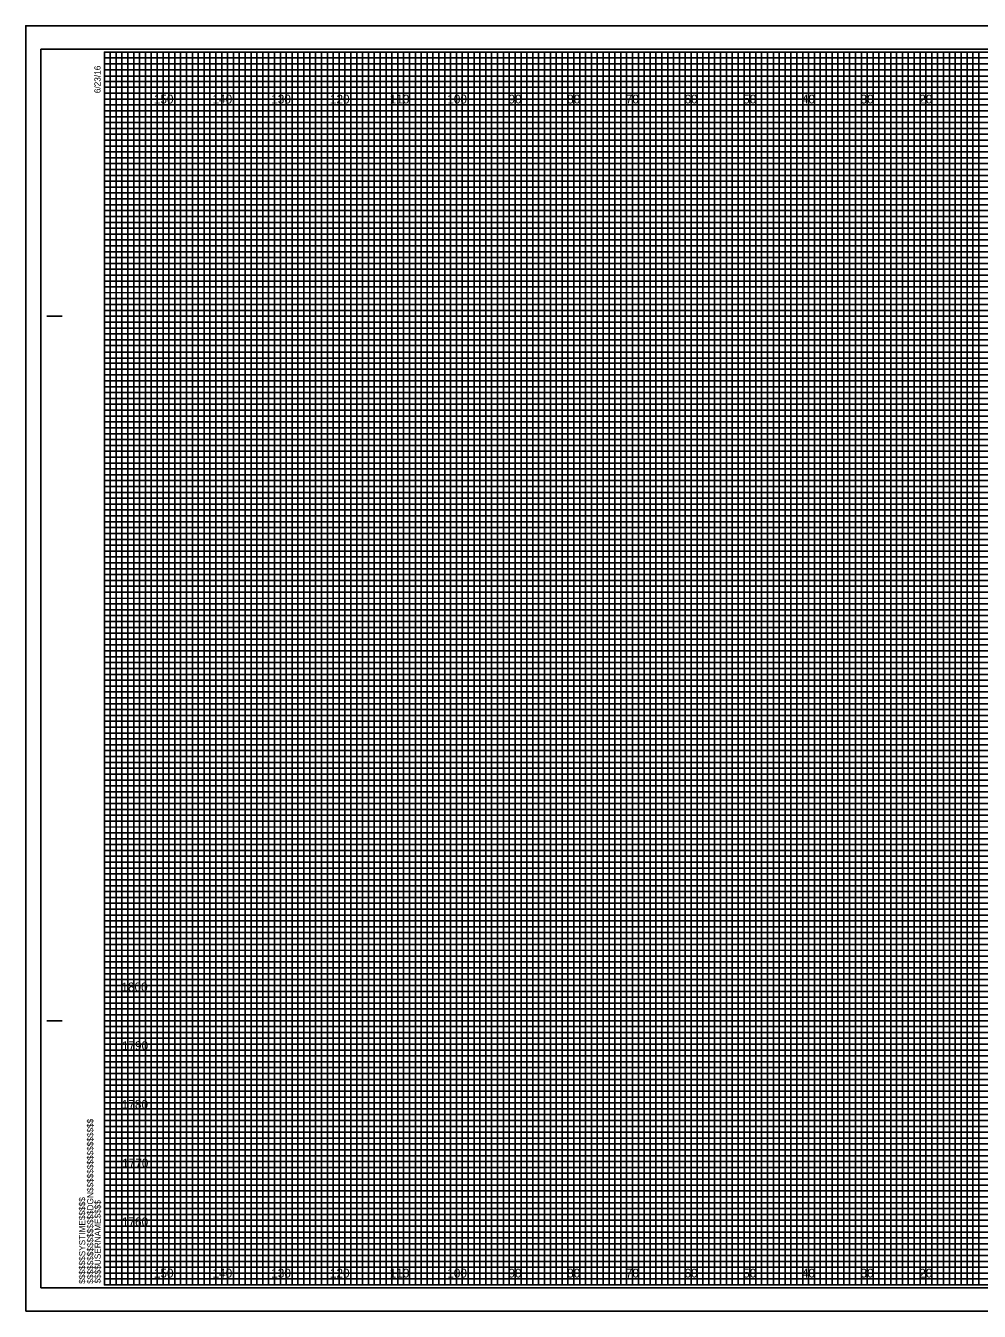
# Model space of a CAD drawing. Extents: x -412 to -75, y -2 to 657.
# Drawn here: x -412.2 to -249.7, y 438.1 to 657.1 of the extents above; entities that cross this region are included whole.
import ezdxf

# ---------------------------------------------------------------- set-up
doc = ezdxf.new("R2010")
doc.units = 0
for name, color, linetype in [('Prop XS Elevation Labels', 7, 'Continuous'), ('Prop XS Offset Labels', 7, 'Continuous'), ('Sheet Cross Section CELL', 7, 'Continuous'), ('Sheet Cross Section Grid Major CELL', 7, 'Continuous'), ('Sheet Cross Section Grid Middle CELL', 7, 'Continuous'), ('Sheet Cross Section Grid Minor 1 CELL', 7, 'Continuous'), ('Sheet Cross Section Grid Minor 2 CELL', 7, 'Continuous'), ('Sheet Cutting Line CELL', 7, 'Continuous'), ('Sheet DOT Grid CELL', 7, 'Continuous'), ('Sheet Plot Border Inside CELL', 7, 'Continuous'), ('Sheet Plot Border Outside CELL', 7, 'Continuous')]:
    doc.layers.add(name, color=color, linetype=linetype)

msp = doc.modelspace()

# ---------------------------------------------------------------- linework, layer by layer
at = {"layer": 'Sheet Cross Section CELL'}
for p, q in [((-408.55, 607.57), (-406.05, 607.57)), ((-408.45, 607.57), (-405.95, 607.57)), ((-408.55, 487.57), (-406.05, 487.57)), ((-408.45, 487.57), (-405.95, 487.57)), ((-398.75, 442.57), (-398.75, 442.57)), ((-398.75, 442.57), (-398.75, 442.57)), ((-398.75, 442.57), (-398.75, 442.57)), ((-398.75, 442.57), (-398.75, 442.57)), ((-398.75, 442.57), (-398.75, 442.57)), ((-398.75, 442.57), (-398.75, 442.57)), ((-398.75, 442.57), (-398.75, 442.57))]:
    msp.add_line(p, q, dxfattribs=at)
msp.add_lwpolyline([(-78.75, 652.57), (-398.75, 652.57), (-398.75, 442.57), (-78.75, 442.57)], close=True, dxfattribs=at)
at = {"layer": 'Sheet Cross Section Grid Major CELL'}
for p, q in [((-388.75, 652.57), (-398.75, 652.57)), ((-388.75, 442.57), (-388.75, 652.57)), ((-368.75, 652.57), (-378.75, 652.57)), ((-378.75, 652.57), (-378.75, 442.57)), ((-368.75, 442.57), (-368.75, 652.57)), ((-348.75, 652.57), (-358.75, 652.57)), ((-358.75, 652.57), (-358.75, 442.57)), ((-348.75, 442.57), (-348.75, 652.57)), ((-328.75, 652.57), (-338.75, 652.57)), ((-338.75, 652.57), (-338.75, 442.57)), ((-328.75, 442.57), (-328.75, 652.57)), ((-308.75, 652.57), (-318.75, 652.57)), ((-318.75, 652.57), (-318.75, 442.57)), ((-308.75, 442.57), (-308.75, 652.57)), ((-288.75, 652.57), (-298.75, 652.57)), ((-298.75, 652.57), (-298.75, 442.57)), ((-288.75, 442.57), (-288.75, 652.57)), ((-268.75, 652.57), (-278.75, 652.57)), ((-278.75, 652.57), (-278.75, 442.57)), ((-268.75, 442.57), (-268.75, 652.57)), ((-248.75, 652.57), (-258.75, 652.57)), ((-258.75, 652.57), (-258.75, 442.57)), ((-378.75, 442.57), (-388.75, 442.57)), ((-358.75, 442.57), (-368.75, 442.57)), ((-338.75, 442.57), (-348.75, 442.57)), ((-318.75, 442.57), (-328.75, 442.57)), ((-298.75, 442.57), (-308.75, 442.57)), ((-278.75, 442.57), (-288.75, 442.57)), ((-258.75, 442.57), (-268.75, 442.57))]:
    msp.add_line(p, q, dxfattribs=at)
for points in [[(-398.75, 642.57), (-78.75, 642.57), (-78.75, 632.57), (-398.75, 632.57)], [(-398.75, 622.57), (-78.75, 622.57), (-78.75, 612.57), (-398.75, 612.57)], [(-398.75, 602.57), (-78.75, 602.57), (-78.75, 592.57), (-398.75, 592.57)], [(-398.75, 582.57), (-78.75, 582.57), (-78.75, 572.57), (-398.75, 572.57)], [(-398.75, 562.57), (-78.75, 562.57), (-78.75, 552.57), (-398.75, 552.57)], [(-398.75, 542.57), (-78.75, 542.57), (-78.75, 532.57), (-398.75, 532.57)], [(-398.75, 522.57), (-78.75, 522.57), (-78.75, 512.57), (-398.75, 512.57)], [(-398.75, 502.57), (-78.75, 502.57), (-78.75, 492.57), (-398.75, 492.57)], [(-398.75, 482.57), (-78.75, 482.57), (-78.75, 472.57), (-398.75, 472.57)], [(-398.75, 462.57), (-78.75, 462.57), (-78.75, 452.57), (-398.75, 452.57)]]:
    msp.add_lwpolyline(points, dxfattribs=at)
at = {"layer": 'Sheet Cross Section Grid Middle CELL'}
for points in [[(-398.75, 652.57), (-393.75, 652.57), (-393.75, 442.57), (-383.75, 442.57), (-383.75, 652.57), (-373.75, 652.57), (-373.75, 442.57), (-363.75, 442.57), (-363.75, 652.57), (-353.75, 652.57), (-353.75, 442.57), (-343.75, 442.57), (-343.75, 652.57), (-333.75, 652.57), (-333.75, 442.57), (-323.75, 442.57), (-323.75, 652.57), (-313.75, 652.57), (-313.75, 442.57), (-303.75, 442.57), (-303.75, 652.57), (-293.75, 652.57), (-293.75, 442.57), (-283.75, 442.57), (-283.75, 652.57), (-273.75, 652.57), (-273.75, 442.57), (-263.75, 442.57), (-263.75, 652.57), (-253.75, 652.57), (-253.75, 442.57), (-243.75, 442.57)], [(-398.75, 647.57), (-123.75, 647.57)], [(-398.75, 627.57), (-78.75, 627.57), (-78.75, 637.57), (-398.75, 637.57)], [(-398.75, 607.57), (-78.75, 607.57), (-78.75, 617.57), (-398.75, 617.57)], [(-398.75, 587.57), (-78.75, 587.57), (-78.75, 597.57), (-398.75, 597.57)], [(-398.75, 567.57), (-78.75, 567.57), (-78.75, 577.57), (-398.75, 577.57)], [(-398.75, 547.57), (-78.75, 547.57), (-78.75, 557.57), (-398.75, 557.57)], [(-398.75, 527.57), (-78.75, 527.57), (-78.75, 537.57), (-398.75, 537.57)], [(-398.75, 507.57), (-78.75, 507.57), (-78.75, 517.57), (-398.75, 517.57)], [(-398.75, 487.57), (-78.75, 487.57), (-78.75, 497.57), (-398.75, 497.57)], [(-398.75, 467.57), (-78.75, 467.57), (-78.75, 477.57), (-398.75, 477.57)], [(-398.75, 447.57), (-78.75, 447.57), (-78.75, 457.57), (-398.75, 457.57)]]:
    msp.add_lwpolyline(points, dxfattribs=at)
at = {"layer": 'Sheet Cross Section Grid Minor 1 CELL'}
for p, q in [((-398.75, 651.57), (-138.75, 651.57)), ((-138.75, 650.55), (-398.75, 650.55)), ((-398.75, 650.55), (-398.75, 649.57)), ((-398.75, 649.57), (-138.75, 649.57)), ((-138.75, 648.46), (-398.75, 648.46)), ((-398.75, 648.46), (-398.75, 646.57)), ((-398.75, 646.57), (-78.75, 646.57))]:
    msp.add_line(p, q, dxfattribs=at)
for points in [[(-398.75, 645.57), (-128.75, 645.57), (-78.75, 645.57), (-78.75, 644.57), (-398.75, 644.57)], [(-398.75, 643.57), (-78.75, 643.57), (-78.75, 641.57), (-398.75, 641.57)], [(-398.75, 640.57), (-78.75, 640.57), (-78.75, 639.57), (-398.75, 639.55)], [(-398.75, 638.57), (-78.75, 638.57), (-78.75, 636.57), (-398.75, 636.57)], [(-398.75, 635.57), (-78.75, 635.57), (-78.75, 634.57), (-398.75, 634.57)], [(-398.75, 633.57), (-78.75, 633.57), (-78.75, 631.57), (-398.75, 631.57)], [(-398.75, 630.57), (-78.75, 630.57), (-78.75, 629.57), (-398.75, 629.57)], [(-398.75, 628.57), (-78.75, 628.57), (-78.75, 626.57), (-398.75, 626.57)], [(-398.75, 625.57), (-78.75, 625.57), (-78.75, 624.57), (-398.75, 624.57)], [(-398.75, 623.57), (-78.75, 623.57), (-78.75, 621.57), (-398.75, 621.57)], [(-398.75, 620.57), (-78.75, 620.57), (-78.75, 619.57), (-398.75, 619.57)], [(-398.75, 618.57), (-78.75, 618.57), (-78.75, 616.52), (-78.75, 615.57), (-78.75, 614.57), (-398.75, 614.57)], [(-398.75, 616.57), (-78.75, 616.57), (-78.75, 615.57), (-398.75, 615.57)], [(-398.75, 613.57), (-78.75, 613.57), (-78.75, 611.57), (-398.75, 611.6)], [(-398.75, 611.6), (-78.75, 611.57), (-78.75, 610.57), (-398.75, 610.57)], [(-398.75, 609.57), (-78.75, 609.57), (-78.75, 608.57), (-398.75, 608.57)], [(-398.75, 606.57), (-78.75, 606.57), (-78.75, 605.57), (-398.75, 605.57)], [(-398.75, 604.57), (-78.75, 604.57), (-78.75, 603.57), (-398.75, 603.57)], [(-398.82, 601.46), (-78.75, 601.46), (-78.75, 600.45), (-398.82, 600.45)], [(-398.75, 599.57), (-78.75, 599.57), (-78.75, 598.57), (-398.75, 598.57)], [(-398.75, 596.57), (-78.75, 596.57), (-78.75, 595.57), (-398.75, 595.57)], [(-398.75, 594.57), (-78.75, 594.57), (-78.75, 593.57), (-398.75, 593.57)], [(-398.75, 591.57), (-78.75, 591.57), (-78.75, 590.57), (-398.75, 590.57)], [(-398.75, 589.57), (-78.75, 589.57), (-78.75, 588.57), (-398.75, 588.57)], [(-398.75, 586.57), (-78.75, 586.57), (-78.75, 585.57), (-398.75, 585.57)], [(-398.75, 584.57), (-78.75, 584.57), (-78.75, 583.57), (-398.75, 583.57)], [(-398.75, 581.57), (-78.75, 581.57), (-78.76, 580.55), (-398.75, 580.57)], [(-398.75, 579.57), (-78.75, 579.57), (-78.75, 578.57), (-398.75, 578.57)], [(-398.75, 576.57), (-78.75, 576.57), (-78.75, 575.57), (-398.75, 575.57)], [(-398.75, 574.57), (-78.75, 574.57), (-78.75, 573.57), (-398.75, 573.57)], [(-398.75, 571.57), (-78.75, 571.57), (-78.75, 570.57), (-398.75, 570.57)], [(-398.75, 569.57), (-78.75, 569.57), (-78.75, 568.57), (-398.75, 568.57)], [(-398.75, 566.57), (-78.75, 566.57), (-78.75, 565.57), (-398.75, 565.57)], [(-398.75, 564.57), (-78.75, 564.57), (-78.75, 563.57), (-398.75, 563.57)], [(-398.75, 561.57), (-78.75, 561.57), (-78.75, 560.57), (-398.75, 560.57)], [(-398.75, 559.56), (-78.68, 559.48), (-78.75, 558.57), (-398.75, 558.57)], [(-398.75, 556.57), (-78.75, 556.57), (-78.75, 555.57), (-398.75, 555.57)], [(-398.75, 554.57), (-78.75, 554.57), (-78.75, 553.57), (-398.75, 553.57)], [(-398.75, 551.57), (-78.75, 551.57), (-78.75, 550.57), (-398.75, 550.57)], [(-398.75, 549.57), (-78.75, 549.57), (-78.75, 548.57), (-398.75, 548.57)], [(-398.75, 546.57), (-78.75, 546.57), (-78.75, 545.57), (-398.75, 545.57)], [(-398.75, 544.57), (-78.75, 544.57), (-78.75, 543.57), (-398.75, 543.57)], [(-398.75, 541.57), (-78.75, 541.57), (-78.75, 540.57), (-398.75, 540.57)], [(-398.75, 539.57), (-78.75, 539.57), (-78.75, 538.57), (-398.75, 538.57)], [(-398.75, 536.57), (-78.75, 536.57), (-78.75, 535.57), (-398.75, 535.57)], [(-398.75, 534.57), (-78.75, 534.57), (-78.75, 533.57), (-398.75, 533.57)], [(-398.75, 531.57), (-78.75, 531.57), (-78.75, 530.57), (-398.75, 530.57)], [(-398.75, 529.57), (-78.75, 529.57), (-78.75, 528.57), (-398.75, 528.57)], [(-398.75, 526.57), (-78.75, 526.57), (-78.75, 525.57), (-398.75, 525.57)], [(-398.75, 524.57), (-78.75, 524.57), (-78.75, 523.57), (-398.75, 523.57)], [(-398.75, 521.57), (-78.75, 521.57), (-78.76, 520.55), (-398.75, 520.57)], [(-398.75, 519.57), (-78.75, 519.57), (-78.75, 518.57), (-398.75, 518.57)], [(-398.75, 516.57), (-78.75, 516.57), (-78.75, 515.57), (-398.75, 515.57)], [(-398.75, 514.57), (-78.75, 514.57), (-78.75, 513.57), (-398.75, 513.57)], [(-398.75, 511.57), (-78.75, 511.57), (-78.75, 510.57), (-398.75, 510.57)], [(-398.75, 509.57), (-78.75, 509.57), (-78.75, 508.57), (-398.75, 508.57)], [(-398.75, 506.57), (-78.75, 506.57), (-78.75, 505.57), (-398.75, 505.57)], [(-398.75, 504.57), (-78.75, 504.57), (-78.75, 503.57), (-398.75, 503.57)], [(-398.75, 501.57), (-78.75, 501.57), (-78.75, 500.57), (-398.75, 500.57)], [(-398.75, 499.56), (-78.68, 499.48), (-78.75, 498.57), (-398.75, 498.57)], [(-398.75, 496.57), (-78.75, 496.57), (-78.75, 495.57), (-398.75, 495.57)], [(-398.75, 494.57), (-78.75, 494.57), (-78.75, 493.57), (-398.75, 493.57)], [(-398.75, 491.57), (-78.75, 491.57), (-78.75, 490.57), (-398.75, 490.57)], [(-398.75, 489.57), (-78.75, 489.57), (-78.75, 488.57), (-398.75, 488.57)], [(-398.75, 486.57), (-78.75, 486.57), (-78.75, 485.57), (-398.75, 485.57)], [(-398.75, 484.57), (-78.75, 484.57), (-78.75, 483.57), (-398.75, 483.57)], [(-398.75, 481.57), (-78.75, 481.57), (-78.75, 480.57), (-398.75, 480.57)], [(-398.75, 479.57), (-78.75, 479.57), (-78.75, 478.57), (-398.75, 478.57)], [(-398.75, 476.57), (-78.75, 476.57), (-78.75, 475.57), (-398.75, 475.57)], [(-398.75, 474.57), (-78.75, 474.57), (-78.75, 473.57), (-398.75, 473.57)], [(-398.75, 471.57), (-78.75, 471.57), (-78.75, 470.57), (-398.75, 470.57)], [(-398.75, 469.57), (-78.75, 469.57), (-78.75, 468.57), (-398.75, 468.57)], [(-398.75, 466.57), (-78.75, 466.57), (-78.75, 465.57), (-398.75, 465.57)], [(-398.75, 464.57), (-78.75, 464.57), (-78.75, 463.57), (-398.75, 463.57)], [(-398.75, 461.57), (-78.75, 461.57), (-78.75, 460.57), (-398.75, 460.57)], [(-398.75, 459.57), (-78.75, 459.57), (-78.75, 458.57), (-398.75, 458.57)], [(-398.75, 456.57), (-78.75, 456.57), (-78.75, 455.57), (-398.75, 455.57)], [(-398.75, 454.57), (-78.75, 454.57), (-78.75, 453.57), (-398.75, 453.57)], [(-398.75, 451.57), (-78.75, 451.57), (-78.75, 450.57), (-398.75, 450.57)], [(-398.75, 449.57), (-78.75, 449.57), (-78.75, 448.57), (-398.75, 448.57)], [(-398.75, 446.57), (-78.75, 446.57), (-78.75, 445.57), (-398.75, 445.57)], [(-398.75, 444.57), (-78.75, 444.57), (-78.75, 443.57), (-398.75, 443.57)]]:
    msp.add_lwpolyline(points, dxfattribs=at)
at = {"layer": 'Sheet Cross Section Grid Minor 2 CELL'}
for points in [[(-398.75, 442.57), (-397.75, 442.57), (-397.75, 652.57), (-396.75, 652.57), (-396.75, 442.57)], [(-396.75, 442.57), (-395.75, 442.57), (-395.75, 652.57), (-394.75, 652.57), (-394.75, 442.57)], [(-393.75, 442.57), (-392.75, 442.57), (-392.75, 652.57), (-391.75, 652.57), (-391.75, 442.57)], [(-391.75, 442.57), (-390.75, 442.57), (-390.75, 652.57), (-389.75, 652.57), (-389.75, 442.57)], [(-388.75, 442.57), (-387.75, 442.57), (-387.75, 652.57), (-386.75, 652.57), (-386.75, 442.57)], [(-386.75, 442.57), (-385.75, 442.57), (-385.75, 652.57), (-384.75, 652.57), (-384.75, 442.57)], [(-383.75, 442.57), (-382.75, 442.57), (-382.75, 652.57), (-381.75, 652.57), (-381.75, 442.57)], [(-381.75, 442.57), (-380.75, 442.57), (-380.75, 652.57), (-379.75, 652.57), (-379.75, 442.57)], [(-378.75, 442.57), (-377.75, 442.57), (-377.75, 652.57), (-376.75, 652.57), (-376.75, 442.57)], [(-376.75, 442.57), (-375.75, 442.57), (-375.75, 652.57), (-374.75, 652.57), (-374.75, 442.57)], [(-373.75, 442.57), (-372.75, 442.57), (-372.75, 652.57), (-371.75, 652.57), (-371.75, 442.57)], [(-371.75, 442.57), (-370.75, 442.57), (-370.75, 652.57), (-369.75, 652.57), (-369.75, 442.57)], [(-368.75, 442.57), (-367.75, 442.57), (-367.75, 652.57), (-366.75, 652.57), (-366.75, 442.57)], [(-366.75, 442.57), (-365.75, 442.57), (-365.75, 652.57), (-364.75, 652.57), (-364.75, 442.57)], [(-363.75, 442.57), (-362.75, 442.57), (-362.75, 652.57), (-361.75, 652.57), (-361.75, 442.57)], [(-361.75, 442.57), (-360.75, 442.57), (-360.75, 652.57), (-359.75, 652.57), (-359.75, 442.57)], [(-358.75, 442.57), (-357.75, 442.57), (-357.75, 652.57), (-356.75, 652.57), (-356.75, 442.57)], [(-356.75, 442.57), (-355.75, 442.57), (-355.75, 652.57), (-354.75, 652.57), (-354.75, 442.57)], [(-353.75, 442.57), (-352.75, 442.57), (-352.75, 652.57), (-351.75, 652.57), (-351.75, 442.57)], [(-351.75, 442.57), (-350.75, 442.57), (-350.75, 652.57), (-349.75, 652.57), (-349.75, 442.57)], [(-348.75, 442.57), (-347.75, 442.57), (-347.75, 652.57), (-346.75, 652.57), (-346.75, 442.57)], [(-346.75, 442.57), (-345.75, 442.57), (-345.75, 652.57), (-344.75, 652.57), (-344.75, 442.57)], [(-343.75, 442.57), (-342.75, 442.57), (-342.75, 652.57), (-341.75, 652.57), (-341.75, 442.57)], [(-341.75, 442.57), (-340.75, 442.57), (-340.75, 652.57), (-339.75, 652.57), (-339.75, 442.57)], [(-338.75, 442.57), (-337.75, 442.57), (-337.75, 652.57), (-336.75, 652.57), (-336.75, 442.57)], [(-336.75, 442.57), (-335.75, 442.57), (-335.75, 652.57), (-334.75, 652.57), (-334.75, 442.57)], [(-333.75, 442.57), (-332.75, 442.57), (-332.75, 652.57), (-331.75, 652.57), (-331.75, 442.57)], [(-331.75, 442.57), (-330.75, 442.57), (-330.75, 652.57), (-329.75, 652.57), (-329.75, 442.57)], [(-328.75, 442.57), (-327.75, 442.57), (-327.75, 652.57), (-326.75, 652.57), (-326.75, 442.57)], [(-326.75, 442.57), (-325.75, 442.57), (-325.75, 652.57), (-324.75, 652.57), (-324.75, 442.57)], [(-323.75, 442.57), (-322.75, 442.57), (-322.75, 652.57), (-321.75, 652.57), (-321.75, 442.57)], [(-321.75, 442.57), (-320.75, 442.57), (-320.75, 652.57), (-319.75, 652.57), (-319.75, 442.57)], [(-318.75, 442.57), (-317.75, 442.57), (-317.75, 652.57), (-316.75, 652.57), (-316.75, 442.57)], [(-316.75, 442.57), (-315.75, 442.57), (-315.75, 652.57), (-314.75, 652.57), (-314.75, 442.57)], [(-313.75, 442.57), (-312.75, 442.57), (-312.75, 652.57), (-311.75, 652.57), (-311.75, 442.57)], [(-311.75, 442.57), (-310.75, 442.57), (-310.75, 652.57), (-309.75, 652.57), (-309.75, 442.57)], [(-308.75, 442.57), (-307.75, 442.57), (-307.75, 652.57), (-306.75, 652.57), (-306.75, 442.57)], [(-306.75, 442.57), (-305.75, 442.57), (-305.75, 652.57), (-304.75, 652.57), (-304.75, 442.57)], [(-303.75, 442.57), (-302.75, 442.57), (-302.75, 652.57), (-301.75, 652.57), (-301.75, 442.57)], [(-301.75, 442.57), (-300.75, 442.57), (-300.75, 652.57), (-299.75, 652.57), (-299.75, 442.57)], [(-298.75, 442.57), (-297.75, 442.57), (-297.75, 652.57), (-296.75, 652.57), (-296.75, 442.57)], [(-296.75, 442.57), (-295.75, 442.57), (-295.75, 652.57), (-294.75, 652.57), (-294.75, 442.57)], [(-293.75, 442.57), (-292.75, 442.57), (-292.75, 652.57), (-291.75, 652.57), (-291.75, 442.57)], [(-291.75, 442.57), (-290.75, 442.57), (-290.75, 652.57), (-289.75, 652.57), (-289.75, 442.57)], [(-288.75, 442.57), (-287.75, 442.57), (-287.75, 652.57), (-286.75, 652.57), (-286.75, 442.57)], [(-286.75, 442.57), (-285.75, 442.57), (-285.75, 652.57), (-284.75, 652.57), (-284.75, 442.57)], [(-283.75, 442.57), (-282.75, 442.57), (-282.75, 652.57), (-281.75, 652.57), (-281.75, 442.57)], [(-281.75, 442.57), (-280.75, 442.57), (-280.75, 652.57), (-279.75, 652.57), (-279.75, 442.57)], [(-278.75, 442.57), (-277.75, 442.57), (-277.75, 652.57), (-276.75, 652.57), (-276.75, 442.57)], [(-276.75, 442.57), (-275.75, 442.57), (-275.75, 652.57), (-274.75, 652.57), (-274.75, 442.57)], [(-273.75, 442.57), (-272.75, 442.57), (-272.75, 652.57), (-271.75, 652.57), (-271.75, 442.57)], [(-271.75, 442.57), (-270.75, 442.57), (-270.75, 652.57), (-269.75, 652.57), (-269.75, 442.57)], [(-268.75, 442.57), (-267.75, 442.57), (-267.75, 652.57), (-266.75, 652.57), (-266.75, 442.57)], [(-266.75, 442.57), (-265.75, 442.57), (-265.75, 652.57), (-264.75, 652.57), (-264.75, 442.57)], [(-263.75, 442.57), (-262.75, 442.57), (-262.75, 652.57), (-261.75, 652.57), (-261.75, 442.57)], [(-261.75, 442.57), (-260.75, 442.57), (-260.75, 652.57), (-259.75, 652.57), (-259.75, 442.57)], [(-258.75, 442.57), (-257.75, 442.57), (-257.75, 652.57), (-256.75, 652.57), (-256.75, 442.57)], [(-256.75, 442.57), (-255.75, 442.57), (-255.75, 652.57), (-254.75, 652.57), (-254.75, 442.57)], [(-253.75, 442.57), (-252.75, 442.57), (-252.75, 652.57), (-251.75, 652.57), (-251.75, 442.57)], [(-251.75, 442.57), (-250.75, 442.57), (-250.75, 652.57), (-249.75, 652.57), (-249.75, 442.57)]]:
    msp.add_lwpolyline(points, dxfattribs=at)
at = {"layer": 'Sheet Cutting Line CELL'}
for p, q in [((-75.45, 657.07), (-412.15, 657.07)), ((-412.15, 657.07), (-412.15, 438.07)), ((-412.15, 438.07), (-75.45, 438.07))]:
    msp.add_line(p, q, dxfattribs=at)
at = {"layer": 'Sheet DOT Grid CELL'}
for p, q in [((-388.75, 442.57), (-388.75, 652.57)), ((-378.75, 442.57), (-378.75, 652.57)), ((-368.75, 442.57), (-368.75, 652.57)), ((-358.75, 442.57), (-358.75, 652.57)), ((-348.75, 442.57), (-348.75, 652.57)), ((-338.75, 442.57), (-338.75, 652.57)), ((-328.75, 442.57), (-328.75, 652.57)), ((-318.75, 442.57), (-318.75, 652.57)), ((-308.75, 442.57), (-308.75, 652.57)), ((-298.75, 442.57), (-298.75, 652.57)), ((-288.75, 442.57), (-288.75, 652.57)), ((-278.75, 442.57), (-278.75, 652.57)), ((-268.75, 442.57), (-268.75, 652.57)), ((-258.75, 442.57), (-258.75, 652.57)), ((-398.75, 642.57), (-78.75, 642.57)), ((-398.75, 632.57), (-78.75, 632.57)), ((-398.75, 622.57), (-78.75, 622.57)), ((-398.75, 612.57), (-78.75, 612.57)), ((-398.75, 602.57), (-78.75, 602.57)), ((-398.75, 592.57), (-78.75, 592.57)), ((-398.75, 582.57), (-78.75, 582.57)), ((-398.75, 572.57), (-78.75, 572.57)), ((-398.75, 562.57), (-78.75, 562.57)), ((-398.75, 552.57), (-78.75, 552.57)), ((-398.75, 542.57), (-78.75, 542.57)), ((-398.75, 532.57), (-78.75, 532.57)), ((-398.75, 522.57), (-78.75, 522.57)), ((-398.75, 512.57), (-78.75, 512.57)), ((-398.75, 502.57), (-78.75, 502.57)), ((-398.75, 492.57), (-78.75, 492.57)), ((-398.75, 482.57), (-78.75, 482.57)), ((-398.75, 472.57), (-78.75, 472.57)), ((-398.75, 462.57), (-78.75, 462.57)), ((-398.75, 452.57), (-78.75, 452.57))]:
    msp.add_line(p, q, dxfattribs=at)
at = {"layer": 'Sheet Plot Border Inside CELL'}
msp.add_lwpolyline([(-409.55, 442.07), (-76.35, 442.07), (-76.35, 653.07), (-409.55, 653.07)], close=True, dxfattribs=at)
at = {"layer": 'Sheet Plot Border Outside CELL'}
msp.add_lwpolyline([(-412.15, 438.07), (-75.45, 438.07), (-75.45, 657.07), (-412.15, 657.07)], close=True, dxfattribs=at)

# ---------------------------------------------------------------- texts
at = {"layer": 'Prop XS Elevation Labels'}
for s, p in [('1800', (-395.83, 492.57)), ('1790', (-395.75, 482.57)), ('1780', (-395.77, 472.57)), ('1770', (-395.71, 462.57)), ('1760', (-395.75, 452.57))]:
    msp.add_text(s, height=1.5, dxfattribs=at).set_placement(p)
at = {"layer": 'Prop XS Offset Labels'}
for s, p in [('150', (-390.31, 643.82)), ('140', (-380.31, 643.82)), ('130', (-370.31, 643.82)), ('120', (-360.31, 643.82)), ('110', (-350.13, 643.82)), ('100', (-340.31, 643.82)), ('90', (-329.89, 643.82)), ('80', (-319.89, 643.82)), ('70', (-309.89, 643.82)), ('60', (-299.89, 643.82)), ('50', (-289.89, 643.82)), ('40', (-279.89, 643.82)), ('30', (-269.89, 643.82)), ('20', (-259.89, 643.82)), ('150', (-390.31, 443.82)), ('140', (-380.31, 443.82)), ('130', (-370.31, 443.82)), ('120', (-360.31, 443.82)), ('110', (-350.13, 443.82)), ('100', (-340.31, 443.82)), ('90', (-329.89, 443.82)), ('80', (-319.89, 443.82)), ('70', (-309.89, 443.82)), ('60', (-299.89, 443.82)), ('50', (-289.89, 443.82)), ('40', (-279.89, 443.82)), ('30', (-269.89, 443.82)), ('20', (-259.89, 443.82))]:
    msp.add_text(s, height=1.5, dxfattribs=at).set_placement(p)
at = {"layer": 'Sheet Cross Section CELL'}
for s, p in [('6/23/16', (-399.4, 645.57)), ('$$$$$$$$$$$$$$$$DGN$$$$$$$$$$$$$$$$', (-400.63, 442.75)), ('$$$$$$SYSTIME$$$$$', (-402.01, 442.75)), ('$$$$USERNAME$$$$', (-399.37, 442.8))]:
    msp.add_text(s, height=1.05, rotation=90, dxfattribs=at).set_placement(p)

doc.saveas('drawing.dxf')
